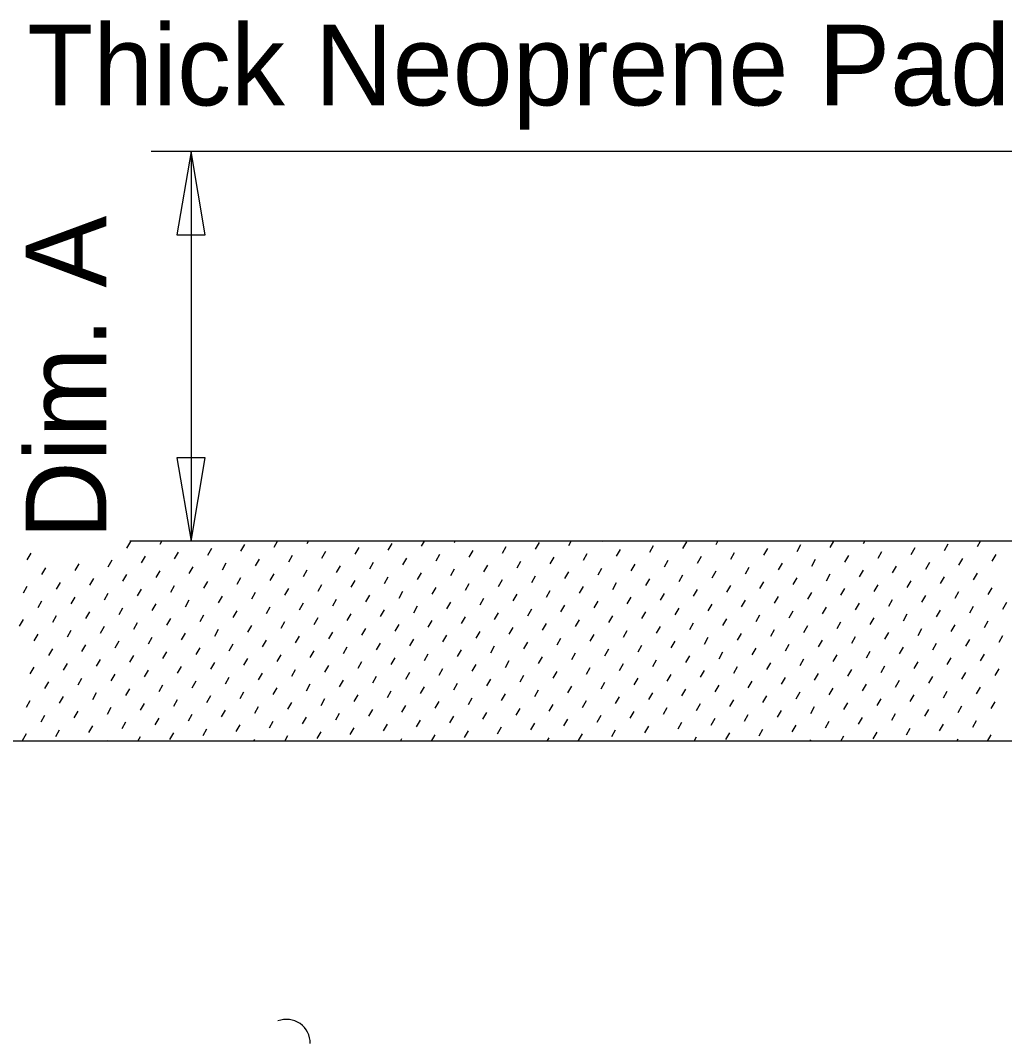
# Model space of a CAD drawing. Extents: x 21652.5 to 21723.2, y 56079.2 to 56117.9.
# Drawn here: x 21680.81 to 21683.271, y 56101.689 to 56104.247 of the extents above; entities that cross this region are included whole.
import ezdxf

# ---------------------------------------------------------------- set-up
doc = ezdxf.new("R2010")
doc.units = 0
for name, color, linetype in [('Dimension', 7, 'Continuous'), ('ExistSuperStruct', 7, 'Continuous'), ('Miscellaneous', 7, 'Continuous'), ('TextStructures', 7, 'Continuous')]:
    doc.layers.add(name, color=color, linetype=linetype)

msp = doc.modelspace()

# ---------------------------------------------------------------- linework, layer by layer
at = {"layer": 'Dimension'}
for p, q in [((21683.6308, 56103.9193), (21681.1366, 56103.9193)), ((21681.2366, 56103.9193), (21681.2366, 56102.9446))]:
    msp.add_line(p, q, dxfattribs=at)
for points in [[(21681.2366, 56103.9193), (21681.2013, 56103.711), (21681.2718, 56103.711)], [(21681.2367, 56102.9446), (21681.2719, 56103.1528), (21681.2014, 56103.1528)]]:
    msp.add_lwpolyline(points, close=True, dxfattribs=at)
msp.add_arc((21681.4753, 56101.6895), 0.0596, 359.2799, 111.0071, dxfattribs=at)
at = {"layer": 'ExistSuperStruct'}
msp.add_line((21683.8894, 56102.4446), (21679.5999, 56102.4446), dxfattribs=at)
at = {"layer": 'Miscellaneous'}
for p, q in [((21681.0761, 56102.9273), (21681.0859, 56102.9441)), ((21683.9447, 56102.9446), (21681.0839, 56102.9446)), ((21681.1591, 56102.937), (21681.1635, 56102.9446)), ((21681.3616, 56102.9199), (21681.3713, 56102.9366)), ((21681.4445, 56102.9296), (21681.4532, 56102.9446)), ((21681.5274, 56102.9393), (21681.5305, 56102.9446)), ((21681.647, 56102.9124), (21681.6567, 56102.9292)), ((21681.7299, 56102.9221), (21681.7396, 56102.9389)), ((21681.8128, 56102.9319), (21681.8202, 56102.9446)), ((21681.8958, 56102.9416), (21681.8975, 56102.9446)), ((21682.0153, 56102.9147), (21682.0251, 56102.9315)), ((21682.0983, 56102.9244), (21682.108, 56102.9412)), ((21682.1812, 56102.9341), (21682.1873, 56102.9446)), ((21682.2641, 56102.9439), (21682.2646, 56102.9446)), ((21682.3837, 56102.917), (21682.3934, 56102.9338)), ((21682.4666, 56102.9267), (21682.4764, 56102.9435)), ((21682.5496, 56102.9364), (21682.5543, 56102.9446)), ((21682.752, 56102.9193), (21682.7618, 56102.9361)), ((21682.835, 56102.929), (21682.844, 56102.9446)), ((21682.9179, 56102.9387), (21682.9213, 56102.9446)), ((21683.0375, 56102.9118), (21683.0472, 56102.9286)), ((21683.1204, 56102.9215), (21683.1301, 56102.9383)), ((21683.2033, 56102.9313), (21683.2111, 56102.9446)), ((21680.8273, 56102.8981), (21680.837, 56102.9149)), ((21681.1127, 56102.8907), (21681.1225, 56102.9075)), ((21681.1957, 56102.9004), (21681.2054, 56102.9172)), ((21681.2786, 56102.9101), (21681.2883, 56102.9269)), ((21681.4811, 56102.893), (21681.4908, 56102.9098)), ((21681.564, 56102.9027), (21681.5738, 56102.9195)), ((21681.7665, 56102.8855), (21681.7762, 56102.9023)), ((21681.8495, 56102.8953), (21681.8592, 56102.912)), ((21681.9324, 56102.905), (21681.9421, 56102.9218)), ((21682.1349, 56102.8878), (21682.1446, 56102.9046)), ((21682.2178, 56102.8975), (21682.2275, 56102.9143)), ((21682.3008, 56102.9073), (21682.3105, 56102.9241)), ((21682.5032, 56102.8901), (21682.513, 56102.9069)), ((21682.5862, 56102.8998), (21682.5959, 56102.9166)), ((21682.6691, 56102.9095), (21682.6788, 56102.9263)), ((21682.8716, 56102.8924), (21682.8813, 56102.9092)), ((21682.9545, 56102.9021), (21682.9643, 56102.9189)), ((21683.157, 56102.8849), (21683.1667, 56102.9017)), ((21683.24, 56102.8947), (21683.2497, 56102.9115)), ((21680.8639, 56102.8615), (21680.8736, 56102.8783)), ((21680.9469, 56102.8712), (21680.9566, 56102.888)), ((21681.0298, 56102.881), (21681.0395, 56102.8978)), ((21681.2323, 56102.8638), (21681.242, 56102.8806)), ((21681.3152, 56102.8735), (21681.3249, 56102.8903)), ((21681.3982, 56102.8832), (21681.4079, 56102.9)), ((21681.6006, 56102.8661), (21681.6104, 56102.8829)), ((21681.6836, 56102.8758), (21681.6933, 56102.8926)), ((21681.969, 56102.8684), (21681.9787, 56102.8852)), ((21682.0519, 56102.8781), (21682.0617, 56102.8949)), ((21682.2544, 56102.8609), (21682.2641, 56102.8777)), ((21682.3374, 56102.8706), (21682.3471, 56102.8874)), ((21682.4203, 56102.8804), (21682.43, 56102.8972)), ((21682.6228, 56102.8632), (21682.6325, 56102.88)), ((21682.7057, 56102.8729), (21682.7154, 56102.8897)), ((21682.7887, 56102.8827), (21682.7984, 56102.8994)), ((21682.9911, 56102.8655), (21683.0009, 56102.8823)), ((21683.0741, 56102.8752), (21683.0838, 56102.892)), ((21680.9835, 56102.8346), (21680.9932, 56102.8514)), ((21681.0664, 56102.8444), (21681.0761, 56102.8611)), ((21681.1493, 56102.8541), (21681.1591, 56102.8709)), ((21681.3518, 56102.8369), (21681.3616, 56102.8537)), ((21681.4348, 56102.8466), (21681.4445, 56102.8634)), ((21681.5177, 56102.8564), (21681.5274, 56102.8732)), ((21681.7202, 56102.8392), (21681.7299, 56102.856)), ((21681.8031, 56102.8489), (21681.8128, 56102.8657)), ((21681.8861, 56102.8586), (21681.8958, 56102.8754)), ((21682.0885, 56102.8415), (21682.0983, 56102.8583)), ((21682.1715, 56102.8512), (21682.1812, 56102.868)), ((21682.374, 56102.834), (21682.3837, 56102.8508)), ((21682.4569, 56102.8438), (21682.4666, 56102.8606)), ((21682.5398, 56102.8535), (21682.5496, 56102.8703)), ((21682.7423, 56102.8363), (21682.752, 56102.8531)), ((21682.8253, 56102.846), (21682.835, 56102.8628)), ((21682.9082, 56102.8558), (21682.9179, 56102.8726)), ((21683.1107, 56102.8386), (21683.1204, 56102.8554)), ((21683.1936, 56102.8483), (21683.2033, 56102.8651)), ((21680.8176, 56102.8152), (21680.8273, 56102.832)), ((21680.9005, 56102.8249), (21680.9103, 56102.8417)), ((21681.186, 56102.8175), (21681.1957, 56102.8343)), ((21681.2689, 56102.8272), (21681.2786, 56102.844)), ((21681.4714, 56102.81), (21681.4811, 56102.8268)), ((21681.5543, 56102.8198), (21681.564, 56102.8365)), ((21681.6373, 56102.8295), (21681.647, 56102.8463)), ((21681.8397, 56102.8123), (21681.8495, 56102.8291)), ((21681.9227, 56102.822), (21681.9324, 56102.8388)), ((21682.0056, 56102.8318), (21682.0153, 56102.8486)), ((21682.2081, 56102.8146), (21682.2178, 56102.8314)), ((21682.291, 56102.8243), (21682.3008, 56102.8411)), ((21682.5765, 56102.8169), (21682.5862, 56102.8337)), ((21682.6594, 56102.8266), (21682.6691, 56102.8434)), ((21682.8619, 56102.8094), (21682.8716, 56102.8262)), ((21682.9448, 56102.8192), (21682.9545, 56102.836)), ((21683.0277, 56102.8289), (21683.0375, 56102.8457)), ((21683.2302, 56102.8117), (21683.24, 56102.8285)), ((21680.9371, 56102.7883), (21680.9469, 56102.8051)), ((21681.0201, 56102.798), (21681.0298, 56102.8148)), ((21681.103, 56102.8077), (21681.1127, 56102.8245)), ((21681.3055, 56102.7906), (21681.3152, 56102.8074)), ((21681.3884, 56102.8003), (21681.3982, 56102.8171)), ((21681.5909, 56102.7831), (21681.6006, 56102.7999)), ((21681.6739, 56102.7929), (21681.6836, 56102.8097)), ((21681.7568, 56102.8026), (21681.7665, 56102.8194)), ((21681.9593, 56102.7854), (21681.969, 56102.8022)), ((21682.0422, 56102.7952), (21682.0519, 56102.8119)), ((21682.1252, 56102.8049), (21682.1349, 56102.8217)), ((21682.3276, 56102.7877), (21682.3374, 56102.8045)), ((21682.4106, 56102.7974), (21682.4203, 56102.8142)), ((21682.4935, 56102.8072), (21682.5032, 56102.824)), ((21682.696, 56102.79), (21682.7057, 56102.8068)), ((21682.7789, 56102.7997), (21682.7887, 56102.8165)), ((21682.9814, 56102.7826), (21682.9911, 56102.7993)), ((21683.0644, 56102.7923), (21683.0741, 56102.8091)), ((21683.1473, 56102.802), (21683.157, 56102.8188)), ((21680.8542, 56102.7786), (21680.8639, 56102.7954)), ((21681.0567, 56102.7614), (21681.0664, 56102.7782)), ((21681.1396, 56102.7711), (21681.1493, 56102.7879)), ((21681.2226, 56102.7809), (21681.2323, 56102.7977)), ((21681.425, 56102.7637), (21681.4348, 56102.7805)), ((21681.508, 56102.7734), (21681.5177, 56102.7902)), ((21681.7934, 56102.766), (21681.8031, 56102.7828)), ((21681.8763, 56102.7757), (21681.8861, 56102.7925)), ((21682.0788, 56102.7585), (21682.0885, 56102.7753)), ((21682.1618, 56102.7683), (21682.1715, 56102.7851)), ((21682.2447, 56102.778), (21682.2544, 56102.7948)), ((21682.4472, 56102.7608), (21682.4569, 56102.7776)), ((21682.5301, 56102.7705), (21682.5398, 56102.7873)), ((21682.6131, 56102.7803), (21682.6228, 56102.7971)), ((21682.8155, 56102.7631), (21682.8253, 56102.7799)), ((21682.8985, 56102.7728), (21682.9082, 56102.7896)), ((21683.1839, 56102.7654), (21683.1936, 56102.7822)), ((21683.2668, 56102.7751), (21683.2766, 56102.7919)), ((21680.8079, 56102.7322), (21680.8176, 56102.749)), ((21680.8908, 56102.742), (21680.9005, 56102.7588)), ((21680.9737, 56102.7517), (21680.9835, 56102.7685)), ((21681.1762, 56102.7345), (21681.186, 56102.7513)), ((21681.2592, 56102.7443), (21681.2689, 56102.761)), ((21681.3421, 56102.754), (21681.3518, 56102.7708)), ((21681.5446, 56102.7368), (21681.5543, 56102.7536)), ((21681.6275, 56102.7465), (21681.6373, 56102.7633)), ((21681.7105, 56102.7563), (21681.7202, 56102.7731)), ((21681.9129, 56102.7391), (21681.9227, 56102.7559)), ((21681.9959, 56102.7488), (21682.0056, 56102.7656)), ((21682.1984, 56102.7317), (21682.2081, 56102.7485)), ((21682.2813, 56102.7414), (21682.291, 56102.7582)), ((21682.3642, 56102.7511), (21682.374, 56102.7679)), ((21682.5667, 56102.7339), (21682.5765, 56102.7507)), ((21682.6497, 56102.7437), (21682.6594, 56102.7605)), ((21682.7326, 56102.7534), (21682.7423, 56102.7702)), ((21682.9351, 56102.7362), (21682.9448, 56102.753)), ((21683.018, 56102.7459), (21683.0277, 56102.7627)), ((21683.101, 56102.7557), (21683.1107, 56102.7725)), ((21681.0104, 56102.7151), (21681.0201, 56102.7319)), ((21681.0933, 56102.7248), (21681.103, 56102.7416)), ((21681.2958, 56102.7076), (21681.3055, 56102.7244)), ((21681.3787, 56102.7174), (21681.3884, 56102.7342)), ((21681.4617, 56102.7271), (21681.4714, 56102.7439)), ((21681.6641, 56102.7099), (21681.6739, 56102.7267)), ((21681.7471, 56102.7197), (21681.7568, 56102.7364)), ((21681.83, 56102.7294), (21681.8397, 56102.7462)), ((21682.0325, 56102.7122), (21682.0422, 56102.729)), ((21682.1154, 56102.7219), (21682.1252, 56102.7387)), ((21682.4009, 56102.7145), (21682.4106, 56102.7313)), ((21682.4838, 56102.7242), (21682.4935, 56102.741)), ((21682.6863, 56102.7071), (21682.696, 56102.7239)), ((21682.7692, 56102.7168), (21682.7789, 56102.7336)), ((21682.8521, 56102.7265), (21682.8619, 56102.7433)), ((21683.0546, 56102.7093), (21683.0644, 56102.7261)), ((21683.1376, 56102.7191), (21683.1473, 56102.7359)), ((21683.2205, 56102.7288), (21683.2302, 56102.7456)), ((21680.8445, 56102.6956), (21680.8542, 56102.7124)), ((21680.9274, 56102.7054), (21680.9371, 56102.7222)), ((21681.1299, 56102.6882), (21681.1396, 56102.705)), ((21681.2128, 56102.6979), (21681.2226, 56102.7147)), ((21681.4153, 56102.6808), (21681.425, 56102.6976)), ((21681.4983, 56102.6905), (21681.508, 56102.7073)), ((21681.5812, 56102.7002), (21681.5909, 56102.717)), ((21681.7837, 56102.683), (21681.7934, 56102.6998)), ((21681.8666, 56102.6928), (21681.8763, 56102.7096)), ((21681.9496, 56102.7025), (21681.9593, 56102.7193)), ((21682.152, 56102.6853), (21682.1618, 56102.7021)), ((21682.235, 56102.6951), (21682.2447, 56102.7118)), ((21682.3179, 56102.7048), (21682.3276, 56102.7216)), ((21682.5204, 56102.6876), (21682.5301, 56102.7044)), ((21682.6033, 56102.6973), (21682.6131, 56102.7141)), ((21682.8058, 56102.6802), (21682.8155, 56102.697)), ((21682.8888, 56102.6899), (21682.8985, 56102.7067)), ((21682.9717, 56102.6996), (21682.9814, 56102.7164)), ((21683.1742, 56102.6825), (21683.1839, 56102.6992)), ((21683.2571, 56102.6922), (21683.2668, 56102.709)), ((21680.8811, 56102.659), (21680.8908, 56102.6758)), ((21680.964, 56102.6688), (21680.9737, 56102.6855)), ((21681.047, 56102.6785), (21681.0567, 56102.6953)), ((21681.2494, 56102.6613), (21681.2592, 56102.6781)), ((21681.3324, 56102.671), (21681.3421, 56102.6878)), ((21681.6178, 56102.6636), (21681.6275, 56102.6804)), ((21681.7007, 56102.6733), (21681.7105, 56102.6901)), ((21681.9032, 56102.6562), (21681.9129, 56102.673)), ((21681.9862, 56102.6659), (21681.9959, 56102.6827)), ((21682.0691, 56102.6756), (21682.0788, 56102.6924)), ((21682.2716, 56102.6584), (21682.2813, 56102.6752)), ((21682.3545, 56102.6682), (21682.3642, 56102.685)), ((21682.4375, 56102.6779), (21682.4472, 56102.6947)), ((21682.6399, 56102.6607), (21682.6497, 56102.6775)), ((21682.7229, 56102.6704), (21682.7326, 56102.6872)), ((21683.0083, 56102.663), (21683.018, 56102.6798)), ((21683.0912, 56102.6727), (21683.101, 56102.6895)), ((21681.0006, 56102.6321), (21681.0104, 56102.6489)), ((21681.0836, 56102.6419), (21681.0933, 56102.6587)), ((21681.1665, 56102.6516), (21681.1762, 56102.6684)), ((21681.369, 56102.6344), (21681.3787, 56102.6512)), ((21681.4519, 56102.6442), (21681.4617, 56102.6609)), ((21681.5349, 56102.6539), (21681.5446, 56102.6707)), ((21681.7374, 56102.6367), (21681.7471, 56102.6535)), ((21681.8203, 56102.6464), (21681.83, 56102.6632)), ((21682.0228, 56102.6293), (21682.0325, 56102.6461)), ((21682.1057, 56102.639), (21682.1154, 56102.6558)), ((21682.1886, 56102.6487), (21682.1984, 56102.6655)), ((21682.3911, 56102.6316), (21682.4009, 56102.6484)), ((21682.4741, 56102.6413), (21682.4838, 56102.6581)), ((21682.557, 56102.651), (21682.5667, 56102.6678)), ((21682.7595, 56102.6338), (21682.7692, 56102.6506)), ((21682.8424, 56102.6436), (21682.8521, 56102.6604)), ((21682.9254, 56102.6533), (21682.9351, 56102.6701)), ((21683.1278, 56102.6361), (21683.1376, 56102.6529)), ((21683.2108, 56102.6458), (21683.2205, 56102.6626)), ((21680.8348, 56102.6127), (21680.8445, 56102.6295)), ((21680.9177, 56102.6224), (21680.9274, 56102.6392)), ((21681.1202, 56102.6053), (21681.1299, 56102.6221)), ((21681.2031, 56102.615), (21681.2128, 56102.6318)), ((21681.2861, 56102.6247), (21681.2958, 56102.6415)), ((21681.4885, 56102.6075), (21681.4983, 56102.6243)), ((21681.5715, 56102.6173), (21681.5812, 56102.6341)), ((21681.6544, 56102.627), (21681.6641, 56102.6438)), ((21681.8569, 56102.6098), (21681.8666, 56102.6266)), ((21681.9398, 56102.6196), (21681.9496, 56102.6363)), ((21682.2253, 56102.6121), (21682.235, 56102.6289)), ((21682.3082, 56102.6218), (21682.3179, 56102.6386)), ((21682.5107, 56102.6047), (21682.5204, 56102.6215)), ((21682.5936, 56102.6144), (21682.6033, 56102.6312)), ((21682.6766, 56102.6241), (21682.6863, 56102.6409)), ((21682.879, 56102.607), (21682.8888, 56102.6238)), ((21682.962, 56102.6167), (21682.9717, 56102.6335)), ((21683.0449, 56102.6264), (21683.0546, 56102.6432)), ((21683.2474, 56102.6092), (21683.2571, 56102.626)), ((21680.9543, 56102.5858), (21680.964, 56102.6026)), ((21681.0372, 56102.5955), (21681.047, 56102.6123)), ((21681.2397, 56102.5784), (21681.2494, 56102.5952)), ((21681.3227, 56102.5881), (21681.3324, 56102.6049)), ((21681.4056, 56102.5978), (21681.4153, 56102.6146)), ((21681.6081, 56102.5807), (21681.6178, 56102.5975)), ((21681.691, 56102.5904), (21681.7007, 56102.6072)), ((21681.774, 56102.6001), (21681.7837, 56102.6169)), ((21681.9764, 56102.5829), (21681.9862, 56102.5997)), ((21682.0594, 56102.5927), (21682.0691, 56102.6095)), ((21682.1423, 56102.6024), (21682.152, 56102.6192)), ((21682.3448, 56102.5852), (21682.3545, 56102.602)), ((21682.4277, 56102.595), (21682.4375, 56102.6117)), ((21682.6302, 56102.5778), (21682.6399, 56102.5946)), ((21682.7132, 56102.5875), (21682.7229, 56102.6043)), ((21682.7961, 56102.5972), (21682.8058, 56102.614)), ((21682.9986, 56102.5801), (21683.0083, 56102.5969)), ((21683.0815, 56102.5898), (21683.0912, 56102.6066)), ((21683.1645, 56102.5995), (21683.1742, 56102.6163)), ((21680.8714, 56102.5761), (21680.8811, 56102.5929)), ((21681.0738, 56102.5589), (21681.0836, 56102.5757)), ((21681.1568, 56102.5687), (21681.1665, 56102.5854)), ((21681.4422, 56102.5612), (21681.4519, 56102.578)), ((21681.5251, 56102.5709), (21681.5349, 56102.5877)), ((21681.7276, 56102.5538), (21681.7374, 56102.5706)), ((21681.8106, 56102.5635), (21681.8203, 56102.5803)), ((21681.8935, 56102.5732), (21681.9032, 56102.59)), ((21682.096, 56102.5561), (21682.1057, 56102.5729)), ((21682.1789, 56102.5658), (21682.1886, 56102.5826)), ((21682.2619, 56102.5755), (21682.2716, 56102.5923)), ((21682.4643, 56102.5583), (21682.4741, 56102.5751)), ((21682.5473, 56102.5681), (21682.557, 56102.5849)), ((21682.8327, 56102.5606), (21682.8424, 56102.5774)), ((21682.9156, 56102.5703), (21682.9254, 56102.5871)), ((21683.1181, 56102.5532), (21683.1278, 56102.57)), ((21683.2011, 56102.5629), (21683.2108, 56102.5797)), ((21680.825, 56102.5298), (21680.8348, 56102.5466)), ((21680.908, 56102.5395), (21680.9177, 56102.5563)), ((21680.9909, 56102.5492), (21681.0006, 56102.566)), ((21681.1934, 56102.532), (21681.2031, 56102.5488)), ((21681.2763, 56102.5418), (21681.2861, 56102.5586)), ((21681.3593, 56102.5515), (21681.369, 56102.5683)), ((21681.5618, 56102.5343), (21681.5715, 56102.5511)), ((21681.6447, 56102.5441), (21681.6544, 56102.5608)), ((21681.8472, 56102.5269), (21681.8569, 56102.5437)), ((21681.9301, 56102.5366), (21681.9398, 56102.5534)), ((21682.013, 56102.5463), (21682.0228, 56102.5631)), ((21682.2155, 56102.5292), (21682.2253, 56102.546)), ((21682.2985, 56102.5389), (21682.3082, 56102.5557)), ((21682.3814, 56102.5486), (21682.3911, 56102.5654)), ((21682.5839, 56102.5315), (21682.5936, 56102.5483)), ((21682.6668, 56102.5412), (21682.6766, 56102.558)), ((21682.7498, 56102.5509), (21682.7595, 56102.5677)), ((21682.9522, 56102.5337), (21682.962, 56102.5505)), ((21683.0352, 56102.5435), (21683.0449, 56102.5603)), ((21680.9446, 56102.5029), (21680.9543, 56102.5197)), ((21681.0275, 56102.5126), (21681.0372, 56102.5294)), ((21681.1105, 56102.5223), (21681.1202, 56102.5391)), ((21681.3129, 56102.5052), (21681.3227, 56102.522)), ((21681.3959, 56102.5149), (21681.4056, 56102.5317)), ((21681.4788, 56102.5246), (21681.4885, 56102.5414)), ((21681.6813, 56102.5074), (21681.691, 56102.5242)), ((21681.7642, 56102.5172), (21681.774, 56102.534)), ((21682.0497, 56102.5097), (21682.0594, 56102.5265)), ((21682.1326, 56102.5195), (21682.1423, 56102.5362)), ((21682.3351, 56102.5023), (21682.3448, 56102.5191)), ((21682.418, 56102.512), (21682.4277, 56102.5288)), ((21682.501, 56102.5217), (21682.5107, 56102.5385)), ((21682.7034, 56102.5046), (21682.7132, 56102.5214)), ((21682.7864, 56102.5143), (21682.7961, 56102.5311)), ((21682.8693, 56102.524), (21682.879, 56102.5408)), ((21683.0718, 56102.5069), (21683.0815, 56102.5237)), ((21683.1547, 56102.5166), (21683.1645, 56102.5334)), ((21683.2377, 56102.5263), (21683.2474, 56102.5431)), ((21680.8616, 56102.4932), (21680.8714, 56102.51)), ((21681.0641, 56102.476), (21681.0738, 56102.4928)), ((21681.1471, 56102.4857), (21681.1568, 56102.5025)), ((21681.23, 56102.4954), (21681.2397, 56102.5122)), ((21681.4325, 56102.4783), (21681.4422, 56102.4951)), ((21681.5154, 56102.488), (21681.5251, 56102.5048)), ((21681.5984, 56102.4977), (21681.6081, 56102.5145)), ((21681.8008, 56102.4806), (21681.8106, 56102.4974)), ((21681.8838, 56102.4903), (21681.8935, 56102.5071)), ((21681.9667, 56102.5), (21681.9764, 56102.5168)), ((21682.1692, 56102.4828), (21682.1789, 56102.4996)), ((21682.2521, 56102.4926), (21682.2619, 56102.5094)), ((21682.4546, 56102.4754), (21682.4643, 56102.4922)), ((21682.5376, 56102.4851), (21682.5473, 56102.5019)), ((21682.6205, 56102.4949), (21682.6302, 56102.5116)), ((21682.823, 56102.4777), (21682.8327, 56102.4945)), ((21682.9059, 56102.4874), (21682.9156, 56102.5042)), ((21682.9889, 56102.4971), (21682.9986, 56102.5139)), ((21683.1913, 56102.48), (21683.2011, 56102.4968)), ((21680.8983, 56102.4565), (21680.908, 56102.4733)), ((21680.9812, 56102.4663), (21680.9909, 56102.4831)), ((21681.2666, 56102.4588), (21681.2763, 56102.4756)), ((21681.3495, 56102.4686), (21681.3593, 56102.4853)), ((21681.552, 56102.4514), (21681.5618, 56102.4682)), ((21681.635, 56102.4611), (21681.6447, 56102.4779)), ((21681.7179, 56102.4708), (21681.7276, 56102.4876)), ((21681.9204, 56102.4537), (21681.9301, 56102.4705)), ((21682.0033, 56102.4634), (21682.013, 56102.4802)), ((21682.0863, 56102.4731), (21682.096, 56102.4899)), ((21682.2887, 56102.456), (21682.2985, 56102.4728)), ((21682.3717, 56102.4657), (21682.3814, 56102.4825)), ((21682.6571, 56102.4582), (21682.6668, 56102.475)), ((21682.74, 56102.468), (21682.7498, 56102.4848)), ((21682.9425, 56102.4508), (21682.9522, 56102.4676)), ((21683.0255, 56102.4605), (21683.0352, 56102.4773)), ((21683.1084, 56102.4703), (21683.1181, 56102.487)), ((21680.8153, 56102.4468), (21680.825, 56102.4636)), ((21681.0265, 56102.4446), (21681.0275, 56102.4465)), ((21681.1038, 56102.4446), (21681.1105, 56102.4562)), ((21681.1837, 56102.4491), (21681.1934, 56102.4659)), ((21681.3935, 56102.4446), (21681.3959, 56102.4487)), ((21681.4708, 56102.4446), (21681.4788, 56102.4585)), ((21681.7605, 56102.4446), (21681.7642, 56102.451)), ((21681.8378, 56102.4446), (21681.8472, 56102.4607)), ((21682.1276, 56102.4446), (21682.1326, 56102.4533)), ((21682.2058, 56102.4462), (21682.2155, 56102.463)), ((21682.4173, 56102.4446), (21682.418, 56102.4459)), ((21682.4946, 56102.4446), (21682.501, 56102.4556)), ((21682.5742, 56102.4485), (21682.5839, 56102.4653)), ((21682.7843, 56102.4446), (21682.7864, 56102.4482)), ((21682.8616, 56102.4446), (21682.8693, 56102.4579)), ((21683.1514, 56102.4446), (21683.1547, 56102.4504)), ((21683.2287, 56102.4446), (21683.2377, 56102.4602))]:
    msp.add_line(p, q, dxfattribs=at)

# ---------------------------------------------------------------- texts
at = {"layer": 'Dimension'}
msp.add_text('Thick Neoprene Pad', height=0.2016, dxfattribs=at).set_placement((21680.8273, 56104.0344))
at = {"layer": 'TextStructures'}
msp.add_text('Dim. A', height=0.2016, rotation=90, dxfattribs=at).set_placement((21681.0247, 56102.9498))

doc.saveas('drawing.dxf')
